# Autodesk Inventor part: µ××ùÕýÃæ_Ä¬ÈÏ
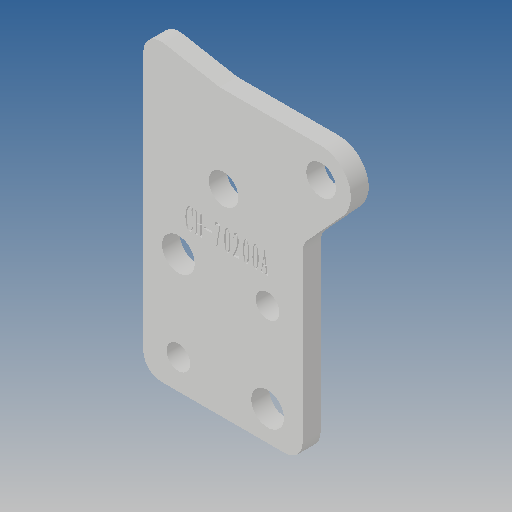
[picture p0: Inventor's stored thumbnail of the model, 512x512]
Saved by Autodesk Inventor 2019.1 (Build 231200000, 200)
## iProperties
Created: 2012-10
Part Number: µ××ùÕýÃæ_Ä¬ÈÏ
Material: Ogólny
Document SubType Name: Modeling
Designer: CADENGINEERING4
Density: 1 g/cm^3
Appearance: Domyślna
Author: CADENGINEERING4
Revision Number: ÈÎºÎ
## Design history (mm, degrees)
feature "NONE"
node "Bryła1"
